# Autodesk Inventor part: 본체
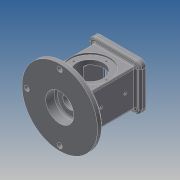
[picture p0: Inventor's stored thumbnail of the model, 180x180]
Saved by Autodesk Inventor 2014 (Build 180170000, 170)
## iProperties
Created: 2019-08
Part Number: 본체
Material: Generic
Document SubType Name: Modeling
Designer: kb542-11
Density: 1 g/cm^3
Appearance: Default
Author: kb542-11
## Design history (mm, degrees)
sketch "스케치1"
  geometry: L1 (-37, -33)-(37, -33); L2 (37, -33)-(37, 33); L3 (37, 33)-(-37, 33); L4 (-37, 33)-(-37, -33); L5 (-37, -33)-(37, 33); L6 (37, -33)-(-37, 33); 1 further point
  constraints: 12 end point, 2 midpoint, 2 parallel, 1 horizontal, 1 perpendicular
  dimensions: "d0" = 74 distance of L2.end L3.end; "d1" = 66 distance of L1.end L2.end
extrude "돌출1" new body sketch "스케치1" distance "d2" = 108; taper "d3" = 0 deg
sketch "스케치2"
  geometry: L1 (-46, -41)-(46, -41); L2 (46, -41)-(46, 41); L3 (46, 41)-(-46, 41); L4 (-46, 41)-(-46, -41); L5 (-46, -41)-(46, 41); L6 (46, -41)-(-46, 41); 1 further point
  constraints: 12 end point, 2 midpoint, 2 parallel, 1 horizontal, 1 perpendicular
  dimensions: "d4" = 92 distance of L2.end L3.end; "d5" = 82 distance between parallel lines of L1 L3
extrude "돌출2" join sketch "스케치2" distance "d6" = 10; taper "d7" = 0 deg
sketch "스케치3"
  geometry: C1 r 67.5 at (0, 0); 1 further point
  constraints: 1 centre point, 1 coincident
  dimensions: "d8" = 135 diameter of C1
extrude "돌출3" join sketch "스케치3" distance "d9" = 10; taper "d10" = 0 deg
sketch "스케치4"
  geometry: L1 (104.5, -98)-(-30.5, -98) reference; C1 r 35 at (37, -44); 1 further point
  constraints: 1 centre point
  dimensions: "d11" = 70 diameter of C1; "d12" = 54 distance from line of L1 C1.centre
extrude "돌출4" cut sketch "스케치4" distance "d13" = 3; taper "d14" = 0 deg
sketch "스케치5"
  geometry: L1 (104.5, -98)-(-30.5, -98) reference; 2 further points
  dimensions: "d15" = 54 distance from line of L1 point (37, -44)
hole "구멍1" sketch "스케치5" at (37, -44) diameter "d16" = 48; stored, may be unused: countersink angle "d20" = 90 deg, drill point angle "d22" = 118 deg; dims "d17" = 6, "d18" = 70, "d19" = 3, "d21" = 8
sketch "스케치6"
  geometry: L1 (-26, -26)-(26, -26); L2 (26, -26)-(26, 26); L3 (26, 26)-(-26, 26); L4 (-26, 26)-(-26, -26); L5 (-26, -26)-(26, 26); L6 (26, -26)-(-26, 26); 1 further point
  constraints: 12 end point, 2 midpoint, 2 parallel, 1 horizontal, 1 perpendicular
  dimensions: "d23" = 52 distance of L2.end L3.end; "d24" = 52 distance of L1.end L2.end
extrude "돌출5" cut sketch "스케치6" distance "d25" = 8; taper "d26" = 0 deg
sketch "스케치7"
  geometry: L1 (-22, -22)-(22, -22); L2 (22, -22)-(22, 22); L3 (22, 22)-(-22, 22); L4 (-22, 22)-(-22, -22); L5 (-22, -22)-(22, 22); L6 (22, -22)-(-22, 22); 1 further point
  constraints: 12 end point, 2 midpoint, 2 parallel, 1 horizontal, 1 perpendicular
  dimensions: "d27" = 44 distance of L2.end L3.end; "d28" = 44 distance of L1.end L2.end
extrude "돌출6" cut sketch "스케치7" distance "d29" = 74; taper "d30" = 0 deg
sketch "스케치8"
  geometry: C1 r 67.5 at (0, 0) reference
hole "구멍2" sketch "스케치8" at (0, 0) diameter "d31" = 25; stored, may be unused: countersink angle "d35" = 90 deg, drill point angle "d37" = 118 deg; dims "d32" = 6, "d33" = 50, "d34" = 18, "d36" = 8
sketch "스케치9"
  geometry: L1 (100.5, -98)-(-34.5, -98) reference; 3 further points
  dimensions: "d38" = 37 distance from line of L1 point (33, -61); "d39" = 43 distance of point (33, -18) point (33, -61)
hole "구멍3" sketch "스케치9" at (33, -61), (33, -18) diameter "d40" = 4.917; stored, may be unused: countersink angle "d44" = 90 deg, drill point angle "d46" = 0 deg; dims "d41" = 6, "d42" = 50, "d43" = 18, "d45" = 20
fillet "모깎기1" dims "d47" = 10
sketch "스케치10"
  geometry: A1 r 10 centre (36, 31) between (46, 31) and (36, 41) reference; A2 r 10 centre (-36, 31) between (-36, 41) and (-46, 31) reference; A3 r 10 centre (-36, -31) between (-46, -31) and (-36, -41) reference; A4 r 10 centre (36, -31) between (36, -41) and (46, -31) reference; 1 further point
hole "구멍4" sketch "스케치10" at (-36, 31), (-36, -31), (36, -31), (36, 31) diameter "d48" = 3.242; stored, may be unused: countersink angle "d52" = 90 deg, drill point angle "d54" = 118 deg; dims "d49" = 4, "d50" = 50, "d51" = 18, "d53" = 6
sketch "스케치11" dims "d55" = 58
  geometry: C1 r 35 at (0, 0) reference; 3 further points
  constraints: 1 coincident, 1 vertical alignment, 2 other
hole "구멍5" sketch "스케치11" at (0, 29) diameter "d56" = 3.242; stored, may be unused: countersink angle "d60" = 90 deg, drill point angle "d62" = 118 deg; dims "d57" = 4, "d58" = 50, "d59" = 18, "d61" = 6
fillet "모깎기2" dims "d66" = 3
fillet "모깎기3" dims "d67" = 3
fillet "모깎기4" dims "d68" = 3
chamfer "모따기1" distance "d69" = 1; stored, may be unused: second distance "d70" = 2, angle "d71" = 45 deg
fillet "모깎기5" dims "d72" = 3
fillet "모깎기6" dims "d73" = 3
fillet "모깎기7" dims "d74" = 3
chamfer "모따기2" distance "d75" = 3; stored, may be unused: second distance "d76" = 2, angle "d77" = 45 deg
sketch "스케치12"
  geometry: C1 r 64.5 at (0, 0) reference; A1 r 59 centre (0, 0) between (0, 59) and (-59, 0); 1 further point
  constraints: 3 point on circle, 1 centre point, 1 coincident
  dimensions: "d78" = 118 diameter of A1
hole "구멍6" sketch "스케치12" at (0, 59), (-59, 0), (0, -59) diameter "d79" = 9; stored, may be unused: countersink angle "d83" = 90 deg, drill point angle "d85" = 118 deg; dims "d80" = 4, "d81" = 50, "d82" = 18, "d84" = 6
sketch "스케치13"
  geometry: C1 r 4.5 at (0, 59) reference; C2 r 64.5 at (0, 0) reference; 1 further point
  constraints: 1 coincident, 1 vertical alignment, 2 other
feature "엠보싱1" sketch "스케치13" dims "d0" = 74, "d1" = 66, "d86" = 0.5, "d87" = 0
node "솔리드1"
pattern_circular "원형 패턴1" dims angle "d64" = 360 deg
mirror "대칭1"
